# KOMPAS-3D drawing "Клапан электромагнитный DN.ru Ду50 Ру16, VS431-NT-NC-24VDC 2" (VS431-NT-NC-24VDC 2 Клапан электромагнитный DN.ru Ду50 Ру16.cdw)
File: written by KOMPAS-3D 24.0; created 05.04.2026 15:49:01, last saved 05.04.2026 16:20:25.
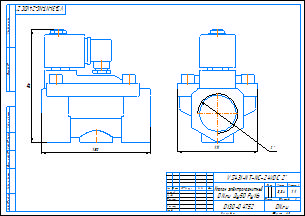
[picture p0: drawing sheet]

Document properties: c3d_UniqueCompID: ef56311e-7521-43dc-8291-0e6108b3d81d; Автор: artio; Класс точности: c; Знак неуказанной шероховатости: Шероховатость не задана; Рассекать на разрезах: Да; c3d_UniqueCompID: ef56311e-7521-43dc-8291-0e6108b3d81d; Автор: artio; Класс точности: c; Знак неуказанной шероховатости: Шероховатость не задана; Рассекать на разрезах: Да; c3d_UniqueCompID: ef56311e-7521-43dc-8291-0e6108b3d81d; Автор: artio; Класс точности: c; Знак неуказанной шероховатости: Шероховатость не задана; Рассекать на разрезах: Да; c3d_UniqueCompID: ef56311e-7521-43dc-8291-0e6108b3d81d; Автор: artio; Класс точности: c; Знак неуказанной шероховатости: Шероховатость не задана; Рассекать на разрезах: Да; c3d_UniqueCompID: ef56311e-7521-43dc-8291-0e6108b3d81d; Автор: artio; Класс точности: c; Знак неуказанной шероховатости: Шероховатость не задана; Рассекать на разрезах: Да; Автор: artio; Форматы листов документа: A3; Полное имя файла: VS431-NT-NC-24VDC 2 Клапан электромагнитный DN.ru Ду50 Ру16.m3d; Масса: 3.341; Наименование: Клапан электромагнитный DN.ru Ду50 Ру16; Количество листов документа: 1; Примечание: D130-04752

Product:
- Body: Тело 1  | qty 1
    Масса: 6.703651
- Part/product: Клапан электромагнитный DN.ru Ду50 Ру16  | designation VS431-NT-NC-24VDC 2
    Масса: 3.341
    Раздел спецификации: Прочие изделия
    Примечание: D130-04752
    additional columns: ef56311e-7521-43dc-8291-0e6108b3d81d; artio; c; Шероховатость не задана; Да

Views: Вид 1, Спереди
Referenced files in C:\Users\artio\OneDrive\Рабочий стол\Клапан электромагнитный DN.ru\VS431\VS431-ET-NC\: VS431-ET-NC-24VDC 3-4 Клапан электромагнитный DN.ru Ду20 Ру16.m3d, VS431-ET-NC-24VDC 3-4 Клапан электромагнитный DN.ru Ду20 Ру16.cdw
Referenced files in C:\Users\artio\OneDrive\Рабочий стол\Клапан электромагнитный DN.ru\VS431\VS431-NT-NC\: VS431-NT-NC-24VDC 2 Клапан электромагнитный DN.ru Ду50 Ру16.m3d
Referenced files in C:\Users\artio\OneDrive\Рабочий стол\Клапан электромагнитный DN.ru\VS431\VS431-NT-NC\VS431-NT-NC-24VDC\Ду50\: VS431-NT-NC-24VDC 2 Клапан электромагнитный DN.ru Ду50 Ру16.m3d
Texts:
  VS431-NT-NC-24VDC 2
  Клапан электромагнитный
  DN.ru Ду50 Ру16
  VS431-NT-NC-24VDC 2"
  VS431-NT-NC-24VDC 2"-
  Клапан электромагнитный DN.ru Ду50 Ру16
  VS431-NT-NC-24VDC 2 Клапан электромагнитный DN.ru Ду50 Ру16
Dimensions and other numbers on the sheet: 0; 3; 2; 4; 111; 1:1; 1; 3,34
